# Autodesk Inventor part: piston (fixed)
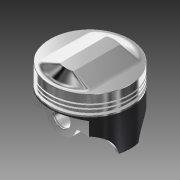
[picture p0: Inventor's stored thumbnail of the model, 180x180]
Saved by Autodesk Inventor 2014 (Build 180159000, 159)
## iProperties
Created: 2001-10
Part Number: piston (fixed)
Document SubType Name: Modeling
Designer: hassen
Density: 1 g/cm^3
Material: Generic
Appearance: Chrome - Polished
Control State: 0
Master: False
Checked Out: False
Shininess: 64.0
Length Units: 11269
Angle Units: 11279
Time Units: 11290
Mass Units: 11283
Length Display Precision: 3
Angle Display Precision: 2
Density: 0.0
Volumn: 0.0
Area: 0.0
PropertySet Name: Model Information
Author: hassen
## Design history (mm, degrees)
sketch "Sketch1"
  geometry: C1 r 40 at (0, 0)
  constraints: 1 centre point
  dimensions: "d0" = 80 diameter of C1
extrude "Extrusion1" new body sketch "Sketch1" distance "d1" = 20 (= 0.25 x d0); taper "d2" = 0 deg
sketch "Sketch2"
  geometry: L1 (-41.357, -15.2)-(-36.8, -15.2); L2 (-36.8, -15.2)-(-36.8, -18.4); L3 (-36.8, -18.4)-(-41.357, -18.4); L4 (-41.357, -18.4)-(-41.357, -15.2); L5 (0, -20.24)-(0, 5.52) reference; L6 (-40, 0)-(40, 0) reference
  constraints: 8 end point, 2 parallel, 1 horizontal, 1 perpendicular
  dimensions: "d3" = 36.8 distance between parallel lines of L5 L2 (= 0.46 x d0); "d4" = 15.2 distance between parallel lines of L6 L1 (= 0.19 x d0); "d5" = 3.2 distance between parallel lines of L3 L1 (= 0.04 x d0)
revolve "Revolution1" sketch "Sketch2" stored, may be unused: angle "d6" = 90 deg
sketch "Sketch3"
  geometry: L1 (-40.464, -12)-(-37.6, -12); L2 (-37.6, -12)-(-37.6, -13.44); L3 (-37.6, -13.44)-(-40.464, -13.44); L4 (-40.464, -13.44)-(-40.464, -12); L5 (0, -14.784)-(0, 4.032) reference; L6 (-40, 0)-(40, 0) reference
  constraints: 8 end point, 2 parallel, 1 horizontal, 1 perpendicular
  dimensions: "d7" = 37.6 distance between parallel lines of L5 L2 (= 0.47 x d0); "d8" = 12 distance between parallel lines of L6 L1 (= 0.15 x d0); "d9" = 1.44 distance between parallel lines of L3 L1 (= 0.018 x d0)
revolve "Revolution2" sketch "Sketch3" stored, may be unused: angle "d10" = 90 deg
pattern_linear "Rectangular Pattern1" dims "d13" = 4
sketch "Sketch4"
  geometry: C1 r 40.028 at (0, 0); 1 further point
  constraints: 1 centre point, 1 coincident
  dimensions: "d14" = 80.056 diameter of C1 (= 1.0007 x d0)
extrude "Extrusion2" join sketch "Sketch4" distance "d15" = 36 (= 0.45 x d0); taper "d16" = 0 deg
sketch "Sketch5"
  geometry: L1 (28.8, -23.2)-(28.8, -63.2); L2 (28.8, -63.2)-(42.4, -63.2); L3 (42.4, -63.2)-(42.4, -20.8); L4 (-40, 0)-(40, 0) reference; L5 (0, -69.52)-(0, 18.96) reference; 1 further point
  constraints: 6 end point, 2 perpendicular, 1 vertical, 3 other
  dimensions: "d17" = 20.8 distance from line of L4 L3.end (= 0.26 x d0); "d18" = 21.6 distance from line of L4 point (36.029, -21.6) (= 0.27 x d0); "d19" = 23.2 distance from line of L4 L1.start (= 0.29 x d0); "d20" = 28.8 distance between parallel lines of L1 L5 (= 0.36 x d0); "d21" = 40 distance of L1.start L1.end (= 0.5 x d0); "d22" = 13.6 distance between parallel lines of L3 L1 (= 0.17 x d0)
extrude "Extrusion3" cut sketch "Sketch5" stored distance "d23" = 28 (= 0.35 x d0); taper "d24" = 0 deg
mirror "Mirror1"
sketch "Sketch8"
  geometry: L1 (32, -36.4)-(32, -60); L2 (32, -60)-(8.8, -60); L3 (0, -66.612)-(0, 18.167) reference; L4 (-40, 0)-(40, 0) reference; 2 further points
  constraints: 4 end point, 1 perpendicular, 1 vertical, 4 other
  dimensions: "d37" = 8.8 distance from line of L3 L2.end (= 0.11 x d0); "d38" = 13.6 distance from line of L3 point (13.6, -46.4) (= 0.17 x d0); "d39" = 21.6 distance from line of L3 point (21.6, -38.8) (= 0.27 x d0); "d40" = 32 distance from line of L3 L1.start (= 0.4 x d0); "d41" = 60 distance from line of L4 L2.end (= 0.75 x d0); "d42" = 46.4 distance from line of L4 point (13.6, -46.4) (= 0.58 x d0); "d43" = 38.8 distance from line of L4 point (21.6, -38.8) (= 0.485 x d0); "d44" = 36.4 distance from line of L4 L1.start (= 0.455 x d0)
extrude "Extrusion6" cut sketch "Sketch8" stored distance "d45" = 32 (= 0.4 x d0); taper "d46" = 0 deg
mirror "Mirror2"
sketch "Sketch11"
  geometry: L1 (-23.89, 25.961)-(24.426, 25.961); L2 (24.426, -25.961)-(-23.89, -25.961); A1 r 40.028 centre (0, 0) between (-38.874, 9.543) and (-38.852, -9.63) reference; A2 r 35.646 centre (0, 0) between (24.426, -25.961) and (24.426, 25.961); A3 r 35.28 centre (0, 0) between (-23.89, 25.961) and (-23.89, -25.961)
  constraints: 4 end point, 4 point on circle, 2 centre point, 1 coincident, 1 horizontal, 1 parallel
  dimensions: "d58" = 35.28 radius of A3 (= 0.441 x d0)
extrude "Extrusion9" cut sketch "Sketch11" distance "d59" = 32 (= 0.4 x d0); taper "d60" = 0 deg
sketch "Sketch12"
  geometry: L1 (-40, 0)-(40, 0) reference; L2 (0, -61.6)-(0, 16.8) reference; L3 (-25.961, -24)-(0, -24); L4 (-25.961, -24)-(0, -24); L5 (9.543, -56)-(-9.63, -56) reference; L6 (0, -13.644)-(0, -24); 5 further points
  constraints: 6 end point, 2 point on line, 1 perpendicular, 6 other
  dimensions: "d65" = 40 distance from line of L5 point (-0.086, -16) (= 0.5 x d0)
revolve "Revolution3" sketch "Sketch12" stored, may be unused: angle "d63" = 90 deg
sketch "Sketch16"
  geometry: L1 (27.799, 0)-(0, 0) reference; L2 (12.662, 12.574)-(10.218, -14.351); L3 (42.916, 12.793)-(45.777, -14.351); L4 (45.777, -14.351)-(10.218, -14.351); L5 (67.799, -23.2)-(-12.201, -23.2) reference; L6 (27.799, 38.4)-(27.799, -40) reference; A1 r 15.2 centre (27.799, 11.2) between (42.916, 12.793) and (12.662, 12.574)
  constraints: 6 end point, 2 point on circle, 2 point on line, 2 tangent, 1 centre point, 1 parallel
  dimensions: "d76" = 30.4 diameter of A1 (= 0.38 x d0); "d82" = 34.4 distance from line of L5 A1.centre (= 0.43 x d0)
extrude "Extrusion11" join sketch "Sketch16" distance "d77" = 14.8 (= 0.185 x d0); taper "d78" = 0 deg
mirror "Mirror3"
sketch "Sketch17"
  geometry: C1 r 8.8 at (0, -34.4); A1 r 15.2 centre (0, -34.4) between (-15.053, -36.511) and (15.053, -36.511) reference
  constraints: 1 centre point, 1 coincident
  dimensions: "d79" = 17.6 diameter of C1 (= 0.22 x d0)
extrude "Extrusion12" cut sketch "Sketch17" stored distance "d80" = 15.2 (= 0.19 x d0); taper "d81" = 0 deg
fillet "Fillet6" dims "d83" = 2
workplane "Work Plane2"
sketch "Sketch18"
  geometry: L1 (-25.319, 23.412)-(-25.319, -23.412); L2 (25.319, 23.412)-(25.319, -23.412); A1 r 36 centre (0, 0) between (-23.596, -27.189) and (23.596, -27.189); A2 r 36 centre (0, 0) between (23.596, 27.189) and (-23.596, 27.189); A3 r 5 centre (-20.319, 23.412) between (-23.596, 27.189) and (-25.319, 23.412); A4 r 5 centre (-20.319, -23.412) between (-25.319, -23.412) and (-23.596, -27.189); A5 r 5 centre (20.319, -23.412) between (23.596, -27.189) and (25.319, -23.412); A6 r 5 centre (20.319, 23.412) between (25.319, 23.412) and (23.596, 27.189)
  constraints: 12 point on circle, 8 tangent, 6 centre point, 4 end point, 3 equal radius, 1 parallel, 1 vertical, 1 other
  dimensions: "d87" = 5 radius of A3
sketch "Sketch19"
  geometry: L1 (-7, 22)-(-7, -22); L2 (7, -22)-(7, 22); A1 r 24.561 centre (0, 0) between (-5.443, -23.95) and (5.443, -23.95); A2 r 24.561 centre (0, 0) between (5.443, 23.95) and (-5.443, 23.95); A3 r 2 centre (-5, 22) between (-5.443, 23.95) and (-7, 22); A4 r 2 centre (5, 22) between (7, 22) and (5.443, 23.95); A5 r 2 centre (-5, -22) between (-7, -22) and (-5.443, -23.95); A6 r 2 centre (5, -22) between (5.443, -23.95) and (7, -22); 1 further point
  constraints: 12 point on circle, 8 tangent, 6 centre point, 4 end point, 3 equal radius, 1 coincident, 1 parallel, 1 vertical
  dimensions: "d90" = 2 radius of A3; "d95" = 22 vertical distance of point (0, 0) A3.centre; "d96" = 22 vertical distance of A6.centre point (0, 0); "d97" = 7 distance from line of point (0, 0) L1; "d98" = 7 distance from line of L2 point (0, 0)
loft "Loft1" sketch "Sketch18", "Sketch19" dims "d91" = 0, "d92" = 90 deg, "d93" = 0, "d94" = 90 deg
sketch "Sketch20"
  geometry: C1 r 40 at (0, 0) reference
extrude "Extrusion13" join sketch "Sketch20" distance "d99" = 0.1; taper "d100" = 0 deg
fillet "Fillet7" dims "d101" = 10
chamfer "Chamfer1" distance "d104" = 0.35; stored, may be unused: second distance "d105" = 0.35, angle "d129" = 45 deg
workplane "Work Plane3"
sketch "Sketch22"
  geometry: L1 (-15.314, 8.044)-(17.744, 8.044); L2 (-13.206, -5.742)-(20.238, -5.742); L3 (17.744, 8.044)-(28.352, 18.965); L4 (20.238, -5.742)-(26.039, -22.033); L5 (-15.314, 8.044)-(-29.027, 17.914); L6 (-13.206, -5.742)-(-27.383, -20.338); A1 r 34.11 centre (0, 0) between (-29.027, 17.914) and (-27.383, -20.338); A2 r 34.11 centre (0, 0) between (26.039, -22.033) and (28.352, 18.965)
  constraints: 12 end point, 4 point on circle, 2 centre point, 2 parallel, 1 horizontal
extrude "Extrusion15" cut sketch "Sketch22" stored distance "d107" = 0.1; taper "d108" = 10 deg
sketch "Sketch23"
  geometry: C1 r 1.465 at (0, -16.787)
  constraints: 1 centre point
extrude "Extrusion16" cut sketch "Sketch23" stored distance "d109" = 0.1; taper "d110" = 0 deg
workplane "Work Plane4"
sketch "Sketch24"
  geometry: C1 r 1.465 at (0, -6.84)
  constraints: 1 centre point, 1 other
  dimensions: "d112" = 2.93 diameter of C1
extrude "Extrusion17" cut sketch "Sketch24" stored distance "d113" = 0.1; taper "d114" = 0 deg
chamfer "Chamfer2" distance "d115" = 0.35; stored, may be unused: second distance "d116" = 0.35, angle "d130" = 45 deg
workplane "Work Plane7"
sketch "Sketch27"
  geometry: C1 r 10.54 at (0, 0)
  constraints: 1 centre point
extrude "Extrusion20" cut sketch "Sketch27" distance "d127" = 1; taper "d128" = 0 deg
mirror "Mirror6"
chamfer "Chamfer3" distance "d121" = 0.35; stored, may be unused: second distance "d122" = 0.35, angle "d131" = 45 deg
body "Solid1"
other parameters: "d56" = 35.28 (= 0.441 x d0), "d84" = 7, "d85" = 72 (= 0.9 x d0), "d88" = 68 (= 0.85 x d0), "d106" = -36 (= -0.45 x d0), "d111" = 90 deg, "d126" = -1.2 (= -0.015 x d0)
